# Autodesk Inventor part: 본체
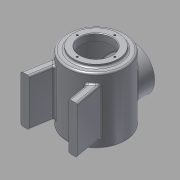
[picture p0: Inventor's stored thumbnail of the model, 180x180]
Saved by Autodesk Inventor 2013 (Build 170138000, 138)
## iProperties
Created: 2015-01
Part Number: 본체
Material: 알루미늄 6061
Document SubType Name: Modeling
Designer: Administrator
Density: 2.71 g/cm^3
Mass: 1058.71 g
Surface Area: 1085.54 cm^2
Volume: 390.668 cm^3
Author: Administrator
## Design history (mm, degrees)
sketch "스케치2"
  geometry: C1 r 50 at (0, 0); 1 further point
  constraints: 1 centre point, 1 coincident
  dimensions: "d0" = 100 diameter of C1
extrude "돌출1" new body sketch "스케치2" distance "d1" = 112; taper "d2" = 0 deg
sketch "스케치3"
  geometry: C1 r 38 at (0, 0); 1 further point
  constraints: 1 centre point, 1 coincident
  dimensions: "d3" = 76 diameter of C1
extrude "돌출2" join sketch "스케치3" distance "d4" = 5; taper "d5" = 0 deg
sketch "스케치4"
  geometry: C1 r 38 at (0, 0); 1 further point
  constraints: 1 centre point, 1 coincident
  dimensions: "d6" = 76 diameter of C1
extrude "돌출3" join sketch "스케치4" distance "d7" = 5; taper "d8" = 0 deg
node "작업 평면2"
  node "작업 평면1"
hole "구멍1" diameter "d25" = 54; stored, may be unused: countersink angle "d29" = 90 deg, drill point angle "d31" = 0 deg; dims "d23" = 10, "d24" = 10, "d26" = 6, "d27" = 4, "d28" = 2, "d30" = 13
hole "구멍2" diameter "d34" = 90; stored, may be unused: countersink angle "d38" = 90 deg, drill point angle "d40" = 0 deg; dims "d32" = 10, "d33" = 10, "d35" = 6, "d36" = 4, "d37" = 2, "d39" = 97
hole "구멍3" diameter "d43" = 54; stored, may be unused: countersink angle "d47" = 90 deg, drill point angle "d49" = 0 deg; dims "d41" = 10, "d42" = 10, "d44" = 6, "d45" = 4, "d46" = 2, "d48" = 12
fillet "모깎기1" dims "d50" = 3
chamfer "모따기1" distance "d51" = 1; stored, may be unused: second distance "d52" = 2, angle "d53" = 45 deg
node "작업 평면3"
sketch "스케치6"
  geometry: L1 (38, 117)-(-38, 117) reference; C1 r 38 at (0, 55); 2 further points
  constraints: 1 centre point, 1 midpoint, 1 vertical alignment
  dimensions: "d58" = 76 diameter of C1; "d59" = 62 distance from line of C1.centre L1
extrude "돌출5" join sketch "스케치6" stored distance "d60" = 80; taper "d61" = 0 deg
hole "구멍4" diameter "d64" = 54; stored, may be unused: countersink angle "d68" = 90 deg, drill point angle "d70" = 0 deg; dims "d62" = 10, "d63" = 10, "d65" = 6, "d66" = 4, "d67" = 2, "d69" = 50
sketch "스케치7"
  geometry: C1 r 38 at (0, 0) reference; 2 further points
  constraints: 1 horizontal alignment
  dimensions: "d71" = 32 distance of C1.centre point (-32, 0)
hole "구멍5" sketch "스케치7" at (-32, 0) diameter "d72" = 3.242; stored, may be unused: countersink angle "d76" = 90 deg, drill point angle "d78" = 118 deg; dims "d73" = 8, "d74" = 4, "d75" = 2, "d77" = 10
sketch "스케치8"
  geometry: C1 r 38 at (0, 0) reference; 2 further points
  constraints: 1 vertical alignment
  dimensions: "d82" = 32 distance of point (0, 0) point (0, 32)
hole "구멍6" sketch "스케치8" at (0, 32) diameter "d83" = 3.242; stored, may be unused: countersink angle "d87" = 90 deg, drill point angle "d89" = 118 deg; dims "d84" = 8, "d85" = 4, "d86" = 2, "d88" = 10
node "작업 평면4"
fillet "모깎기2" dims "d93" = 3
node "작업 평면5"
sketch "스케치9"
  geometry: L1 (-6, 30)-(6, 30); L2 (6, 30)-(6, 84); L3 (6, 84)-(-6, 84); L4 (-6, 84)-(-6, 30); L5 (-38, -5)-(38, -5) reference; 2 further points
  constraints: 8 end point, 2 parallel, 1 horizontal, 1 midpoint, 1 perpendicular, 1 vertical alignment
  dimensions: "d98" = 54 distance between parallel lines of L3 L1; "d100" = 12 distance between parallel lines of L4 L2; "d101" = 35 distance between parallel lines of L1 L5
extrude "돌출6" join sketch "스케치9" stored distance "d102" = 80; taper "d103" = 0 deg
sketch "스케치10"
  geometry: L1 (30, -6)-(30, 6) reference; 3 further points
  constraints: 1 horizontal alignment, 1 midpoint, 1 other
  dimensions: "d104" = 27 distance from line of point (57, 0) L1
feature "엠보싱1" sketch "스케치10" dims "d105" = 0.5, "d106" = 0
chamfer "모따기2" distance "d107" = 1; stored, may be unused: second distance "d108" = 2, angle "d109" = 45 deg
fillet "모깎기6" dims "d110" = 3
fillet "모깎기7" dims "d111" = 3
node "작업 평면6"
sketch "스케치11"
  geometry: L1 (-39.336, -30.865)-(-48, -80); L2 (-27.088, -42.026)-(-33.784, -80); L3 (-48, -80)-(-33.784, -80); L4 (0, 0)-(-50, 0); L5 (0, 0)-(0, -50); A1 r 50 centre (0, 0) between (-39.336, -30.865) and (-27.088, -42.026) reference; 1 further point
  constraints: 10 end point, 4 point on circle, 2 parallel, 1 horizontal, 1 perpendicular
  dimensions: "d117" = 80 distance between parallel lines of L3 L4; "d119" = 14 distance between parallel lines of L2 L1; "d120" = 80 deg angle of L2 L3; "d121" = 48 distance from line of L1.end L5
extrude "돌출7" join sketch "스케치11" stored distance "d122" = 80; taper "d123" = 0 deg
fillet "모깎기8" dims "d124" = 3
fillet "모깎기9" dims "d125" = 3
node "솔리드1"
pattern_circular "원형 패턴1" dims angle "d80" = 360 deg
pattern_circular "원형 패턴2" dims angle "d91" = 360 deg
mirror "대칭2"
mirror "대칭3"
other parameters: "d54" = 62, "d97" = -52
